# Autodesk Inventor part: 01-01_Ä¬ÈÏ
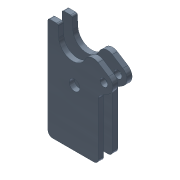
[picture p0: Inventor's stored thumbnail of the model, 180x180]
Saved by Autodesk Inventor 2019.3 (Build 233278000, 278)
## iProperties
Created: 2010-06
Part Number: 01-01_Ä¬ÈÏ
Material: Ogólny
Document SubType Name: Modeling
Designer: CADENGINEERING4
Density: 1 g/cm^3
Appearance: Stal
Author: CADENGINEERING4
Revision Number: ÈÎºÎ
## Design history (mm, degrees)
feature "NONE"
feature "NONE:1"
node "Bryła1"
node "Bryła2"
